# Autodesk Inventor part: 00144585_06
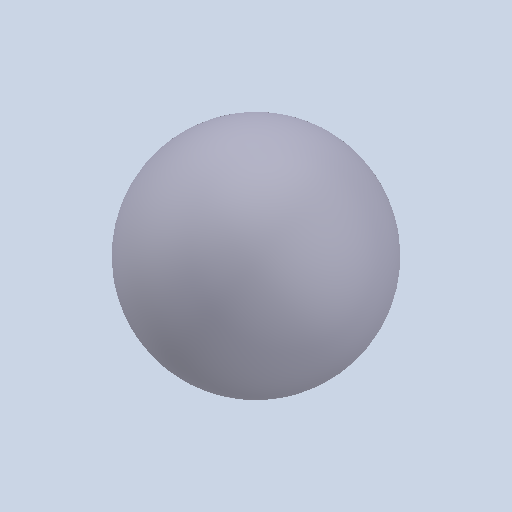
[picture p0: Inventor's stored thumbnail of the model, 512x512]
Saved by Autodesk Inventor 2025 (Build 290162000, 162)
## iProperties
Created: 2021-02
Part Number: 00144585_06
Material: Generico
Document SubType Name: Modeling
Designer: Ryzen5700u
Density: 1 g/cm^3
Appearance: Default
Author: Ryzen5700u
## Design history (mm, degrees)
feature "Solido1"
node "Solido2"
